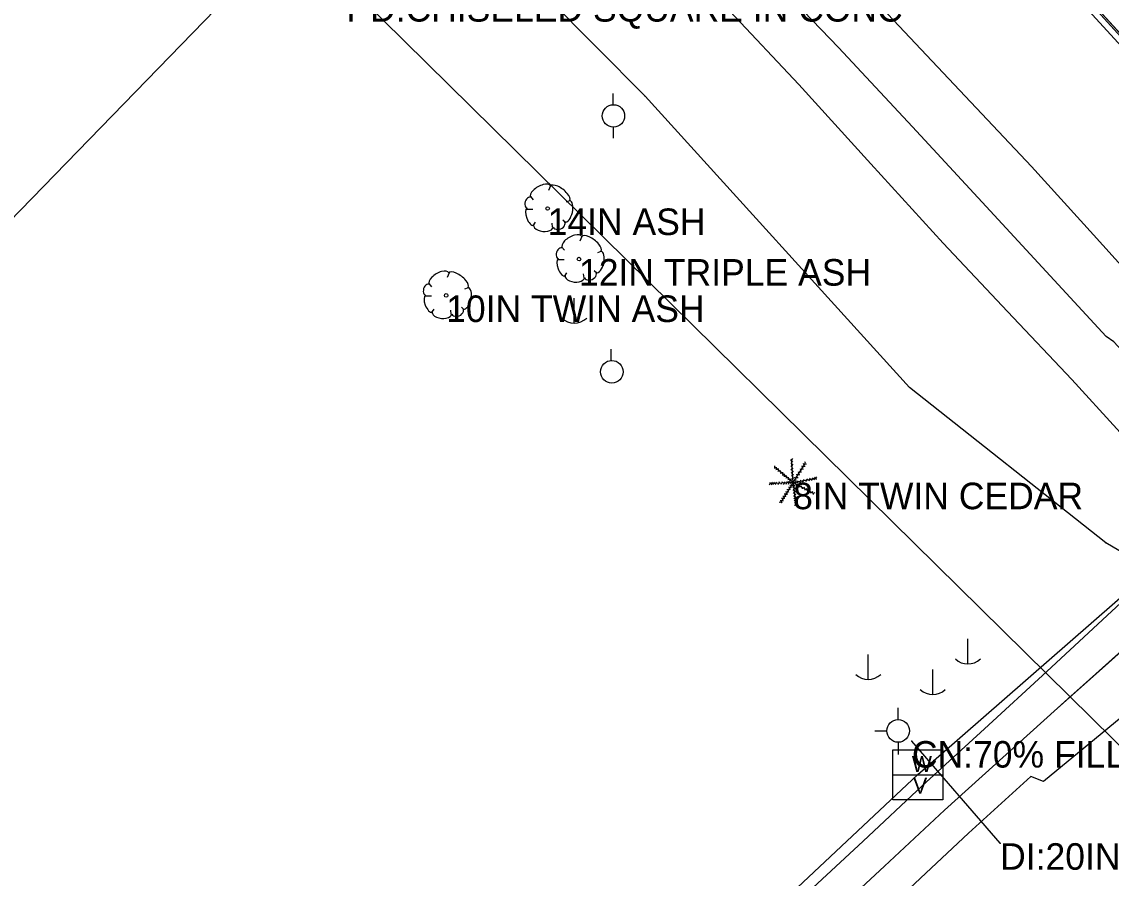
# Model space of a CAD drawing. Extents: x 1660112 to 1662239, y 668919 to 671377.
# Drawn here: x 1661239.8 to 1661444.9, y 669974.4 to 670135.7 of the extents above; entities that cross this region are included whole.
import ezdxf

# ---------------------------------------------------------------- set-up
doc = ezdxf.new("R2010")
doc.units = 0
for name, color, linetype in [('S_DITCHLINE', 7, 'Continuous'), ('S_DRG_PT_SYM', 7, 'Continuous'), ('S_EDGE_PAVEMENT', 7, 'Continuous'), ('S_FENCE', 7, 'Continuous'), ('S_PAVEMENT_CROWN', 7, 'Continuous'), ('S_PRIMARY_CTL_ANNOT', 7, 'Continuous'), ('S_SANITARY_SEWER', 7, 'Continuous'), ('S_SIDE_DRAIN', 7, 'Continuous'), ('S_SIDE_DRAIN_ANNOT', 7, 'Continuous'), ('S_TREE', 7, 'Continuous'), ('S_TREE_ANNOT', 7, 'Continuous'), ('S_UTILITY_POLE', 7, 'Continuous'), ('S_UTL_PT_SYM', 7, 'Continuous'), ('S_WATER_UTILITIES', 7, 'Continuous')]:
    doc.layers.add(name, color=color, linetype=linetype)

msp = doc.modelspace()

# ---------------------------------------------------------------- linework, layer by layer
at = {"layer": 'S_DITCHLINE'}
for points in [[(1661495.46, 670073.89), (1661482.85, 670088.25), (1661470.25, 670102.6), (1661470.41, 670103.23), (1661460.8, 670115.6), (1661451.19, 670127.97), (1661437.9, 670142.65), (1661424.62, 670157.34), (1661411.2, 670172.34), (1661397.77, 670187.35), (1661386.72, 670199.36), (1661375.66, 670211.37), (1661356.56, 670219.75), (1661346.24, 670231.99), (1661335.91, 670244.22), (1661322, 670253.4)], [(1661494.51, 670072.98), (1661481.63, 670087.01), (1661468.75, 670101.04), (1661468.56, 670102.05), (1661459.49, 670114.59), (1661450.42, 670127.12), (1661437.16, 670141.71), (1661423.9, 670156.29), (1661409.97, 670171.2), (1661396.04, 670186.11), (1661384.96, 670198.23), (1661373.87, 670210.36), (1661354.32, 670219.23), (1661344.06, 670230.9), (1661333.8, 670242.57), (1661320.4, 670253.01)]]:
    msp.add_lwpolyline(points, dxfattribs=at)
at = {"layer": 'S_DRG_PT_SYM'}
for points in [[(1661407.39, 670000.2), (1661407.39, 670000.25), (1661407.39, 670000.2), (1661407.34, 670000.2), (1661407.39, 670000.2), (1661407.39, 670000.15), (1661407.39, 670000.2), (1661407.44, 670000.2)], [(1661424, 669980.96), (1661424, 669981.01), (1661424, 669980.96), (1661423.95, 669980.96), (1661424, 669980.96), (1661424, 669980.91), (1661424, 669980.96), (1661424.05, 669980.96)]]:
    msp.add_lwpolyline(points, dxfattribs=at)
at = {"layer": 'S_EDGE_PAVEMENT'}
for points in [[(1661528.89, 670006.64), (1661525.81, 670010.93), (1661521.19, 670007.06), (1661512.12, 670017.42), (1661503.06, 670027.78), (1661494.14, 670038.45), (1661485.22, 670049.12), (1661475.65, 670058.13), (1661469.7, 670064.69), (1661453.26, 670082.63), (1661441.58, 670095.54), (1661429.9, 670108.45), (1661415.33, 670123.89), (1661400.76, 670139.32), (1661387.62, 670152.61), (1661374.47, 670165.9), (1661358.81, 670181.9), (1661343.14, 670197.9), (1661339.48, 670201.44), (1661329.75, 670211.05), (1661320.02, 670220.65), (1661304.77, 670236.19)], [(1661507.57, 669985.17), (1661503.63, 669990.55), (1661503.83, 669996.41), (1661492.59, 670008.33), (1661484.98, 670015.56), (1661475.91, 670025.37), (1661466.84, 670035.18), (1661454.4, 670049.73), (1661445.95, 670059), (1661437.51, 670068.28), (1661425.39, 670081.13), (1661413.28, 670093.99), (1661399.68, 670108.94), (1661386.08, 670123.89), (1661373.13, 670137.66), (1661360.18, 670151.43), (1661345.14, 670167.24), (1661330.11, 670183.04), (1661325.69, 670187.24), (1661316.74, 670196.41), (1661307.8, 670205.57), (1661291.28, 670222.16)], [(1661249.19, 669845.77), (1661252.39, 669848.76), (1661268.86, 669863.99), (1661278.76, 669872.97), (1661288.66, 669881.95), (1661300.04, 669892.31), (1661311.42, 669902.66), (1661327.02, 669916.7), (1661339.16, 669927.65), (1661351.29, 669938.61), (1661369.17, 669954.79), (1661387.06, 669970.96), (1661398.2, 669981.35), (1661409.34, 669991.75), (1661421.08, 670002.53), (1661432.82, 670013.32), (1661449.38, 670028.66), (1661451.32, 670030.24), (1661455.87, 670040.73), (1661454.57, 670045.91), (1661454.4, 670049.73)], [(1661484.97, 670015.57), (1661481.44, 670017.1), (1661474.37, 670019.33), (1661466.03, 670019.66), (1661456.43, 670012.6), (1661444.31, 670002.59), (1661432.19, 669992.58), (1661429.76, 669993.52), (1661418.03, 669982.83), (1661399.88, 669965.82), (1661383.18, 669950.54), (1661366.48, 669935.26), (1661355.84, 669925.69), (1661345.19, 669916.12), (1661334.54, 669906.55), (1661323.9, 669896.98), (1661314.39, 669888.26), (1661304.88, 669879.54), (1661295.37, 669870.82), (1661285.87, 669862.1), (1661271.87, 669849.3), (1661257.87, 669836.51)]]:
    msp.add_lwpolyline(points, dxfattribs=at)
at = {"layer": 'S_FENCE'}
msp.add_line((1661463.18, 670115.3), (1661437.44, 670143.55), dxfattribs=at)
msp.add_lwpolyline([(1661447.01, 670133.04), (1661437.44, 670143.55)], dxfattribs=at)
msp.add_lwpolyline([(1661447.01, 670133.04), (1661437.44, 670143.55)], dxfattribs=at)
at = {"layer": 'S_PAVEMENT_CROWN'}
for points in [[(1661518.06, 669996.03), (1661505.4, 670009.31), (1661492.74, 670022.59), (1661480.19, 670036.99), (1661467.64, 670051.39), (1661473.76, 670044.39), (1661461.34, 670057.98), (1661445.4, 670075.38), (1661443.99, 670076.39), (1661432.69, 670088.65), (1661421.39, 670100.9), (1661407.48, 670115.88), (1661393.57, 670130.85), (1661380.41, 670144.59), (1661367.25, 670158.33), (1661351.88, 670174.26), (1661336.51, 670190.18), (1661332.38, 670194.36), (1661323.21, 670203.51), (1661314.05, 670212.66), (1661297.56, 670228.68)], [(1661253.85, 669840.46), (1661263.61, 669849.85), (1661273.37, 669859.23), (1661283.14, 669868.61), (1661292.9, 669878), (1661304.03, 669887.93), (1661315.16, 669897.86), (1661325.53, 669906.87), (1661335.91, 669915.88), (1661346.29, 669924.88), (1661356.66, 669933.89), (1661373.78, 669949.99), (1661390.9, 669966.09), (1661402.21, 669976.63), (1661413.52, 669987.17), (1661425.13, 669997.67), (1661436.73, 670008.16), (1661454.08, 670023.57), (1661444.42, 670014.94), (1661434.75, 670006.32), (1661450.56, 670020.53), (1661466.37, 670034.74)]]:
    msp.add_lwpolyline(points, dxfattribs=at)
at = {"layer": 'S_SANITARY_SEWER'}
for p, q in [((1661289.08, 670151.19), (1660996.93, 669850.58)), ((1661704.02, 669745.54), (1661292.91, 670150.69))]:
    msp.add_line(p, q, dxfattribs=at)
at = {"layer": 'S_SIDE_DRAIN'}
msp.add_line((1661424, 669980.96), (1661407.39, 670000.2), dxfattribs=at)
at = {"layer": 'S_TREE'}
for p, q in [((1661339.36, 670104.75), (1661338.97, 670103.9)), ((1661335.56, 670102.74), (1661336.06, 670102.16)), ((1661342.92, 670101.96), (1661342.26, 670101.69)), ((1661334.9, 670100.41), (1661336.02, 670100.41)), ((1661336.06, 670097.24), (1661336.53, 670097.93)), ((1661339.74, 670096.97), (1661339.67, 670097.74)), ((1661342.15, 670097.86), (1661341.68, 670098.28)), ((1661345.26, 670095.22), (1661344.88, 670094.37)), ((1661341.47, 670093.21), (1661341.97, 670092.63)), ((1661348.83, 670092.43), (1661348.17, 670092.16)), ((1661340.81, 670090.88), (1661341.93, 670090.88)), ((1661320.25, 670088.37), (1661319.86, 670087.52)), ((1661341.97, 670087.7), (1661342.44, 670088.4)), ((1661345.65, 670087.43), (1661345.57, 670088.21)), ((1661348.05, 670088.32), (1661347.59, 670088.75)), ((1661316.45, 670086.36), (1661316.96, 670085.78)), ((1661323.81, 670085.58), (1661323.16, 670085.31)), ((1661315.79, 670084.03), (1661316.92, 670084.03)), ((1661316.96, 670080.86), (1661317.42, 670081.55)), ((1661320.64, 670080.59), (1661320.56, 670081.36)), ((1661323.04, 670081.48), (1661322.57, 670081.9)), ((1661384.76, 670052.95), (1661384.54, 670053.15)), ((1661384.79, 670052.39), (1661384.57, 670052.59)), ((1661385.02, 670048.87), (1661384.75, 670053.31)), ((1661384.76, 670053.2), (1661384.95, 670053.43)), ((1661384.79, 670052.72), (1661384.98, 670052.96)), ((1661384.82, 670052.12), (1661385.01, 670052.36)), ((1661385.02, 670048.87), (1661387.36, 670052.56)), ((1661387.09, 670052.18), (1661387, 670052.47)), ((1661387.22, 670052.34), (1661387.52, 670052.39)), ((1661387.33, 670052.53), (1661387.24, 670052.81)), ((1661381.73, 670051.62), (1661381.44, 670051.58)), ((1661385.02, 670048.87), (1661381.55, 670051.78)), ((1661381.59, 670051.76), (1661381.59, 670052.06)), ((1661382.08, 670051.34), (1661381.78, 670051.31)), ((1661381.91, 670051.51), (1661381.91, 670051.81)), ((1661382.44, 670051.02), (1661382.14, 670050.99)), ((1661382.26, 670051.22), (1661382.26, 670051.52)), ((1661382.9, 670050.64), (1661382.6, 670050.62)), ((1661382.67, 670050.85), (1661382.67, 670051.15)), ((1661383.26, 670050.31), (1661382.96, 670050.29)), ((1661383.09, 670050.53), (1661383.09, 670050.83)), ((1661383.41, 670050.24), (1661383.41, 670050.54)), ((1661383.78, 670049.94), (1661383.78, 670050.24)), ((1661384.82, 670051.82), (1661384.6, 670052.01)), ((1661384.85, 670051.16), (1661384.62, 670051.36)), ((1661384.89, 670050.56), (1661384.66, 670050.76)), ((1661384.93, 670050), (1661384.7, 670050.2)), ((1661384.86, 670051.41), (1661385.05, 670051.65)), ((1661384.92, 670050.85), (1661385.11, 670051.08)), ((1661384.94, 670050.28), (1661385.12, 670050.51)), ((1661385.82, 670050.16), (1661385.73, 670050.44)), ((1661385.98, 670050.37), (1661386.28, 670050.41)), ((1661386.12, 670050.65), (1661386.03, 670050.93)), ((1661386.33, 670050.89), (1661386.63, 670050.93)), ((1661386.49, 670051.22), (1661386.4, 670051.5)), ((1661386.66, 670051.43), (1661386.95, 670051.47)), ((1661386.79, 670051.73), (1661386.7, 670052.02)), ((1661386.98, 670051.92), (1661387.27, 670051.96)), ((1661380.65, 670048.66), (1661380.51, 670048.39)), ((1661385.02, 670048.87), (1661380.56, 670048.66)), ((1661380.8, 670048.68), (1661380.63, 670048.93)), ((1661381, 670048.69), (1661380.86, 670048.42)), ((1661381.18, 670048.71), (1661381.02, 670048.96)), ((1661381.34, 670048.71), (1661381.2, 670048.44)), ((1661381.58, 670048.71), (1661381.42, 670048.96)), ((1661381.76, 670048.72), (1661381.62, 670048.45)), ((1661381.98, 670048.74), (1661381.82, 670048.98)), ((1661382.27, 670048.74), (1661382.13, 670048.48)), ((1661382.55, 670048.75), (1661382.38, 670049)), ((1661385.02, 670048.87), (1661382.64, 670045.1)), ((1661382.83, 670048.77), (1661382.7, 670048.5)), ((1661383.11, 670048.79), (1661382.94, 670049.04)), ((1661383.31, 670048.79), (1661383.18, 670048.52)), ((1661383.6, 670050.05), (1661383.3, 670050.02)), ((1661383.58, 670048.8), (1661383.42, 670049.05)), ((1661383.94, 670049.75), (1661383.64, 670049.73)), ((1661383.78, 670048.82), (1661383.65, 670048.55)), ((1661384.02, 670048.84), (1661383.85, 670049.09)), ((1661384.31, 670049.45), (1661384.01, 670049.43)), ((1661384.24, 670048.82), (1661384.11, 670048.55)), ((1661384.15, 670049.63), (1661384.15, 670049.93)), ((1661384.36, 670048.88), (1661384.19, 670049.13)), ((1661384.67, 670049.16), (1661384.37, 670049.13)), ((1661384.69, 670048.38), (1661384.39, 670048.34)), ((1661384.5, 670049.32), (1661384.5, 670049.62)), ((1661384.63, 670048.83), (1661384.5, 670048.57)), ((1661384.6, 670048.22), (1661384.67, 670047.93)), ((1661384.94, 670049.38), (1661384.71, 670049.58)), ((1661384.81, 670048.55), (1661384.89, 670048.26)), ((1661385.08, 670048.2), (1661384.88, 670047.97)), ((1661384.96, 670049.61), (1661385.15, 670049.84)), ((1661385.02, 670048.87), (1661389.44, 670049.74)), ((1661385.02, 670048.87), (1661388.93, 670046.83)), ((1661385.02, 670048.87), (1661385.55, 670044.5)), ((1661385.09, 670048.45), (1661385.35, 670048.29)), ((1661385.35, 670048.69), (1661385.61, 670048.83)), ((1661385.36, 670049.36), (1661385.66, 670049.41)), ((1661385.46, 670049.63), (1661385.37, 670049.91)), ((1661385.39, 670048.96), (1661385.59, 670049.18)), ((1661385.53, 670048.6), (1661385.6, 670048.3)), ((1661385.64, 670048.99), (1661385.89, 670048.83)), ((1661385.65, 670049.83), (1661385.95, 670049.87)), ((1661385.79, 670049.02), (1661385.99, 670049.24)), ((1661385.82, 670048.47), (1661386.09, 670048.61)), ((1661386.11, 670048.29), (1661386.18, 670048)), ((1661386.15, 670049.07), (1661386.41, 670048.91)), ((1661386.32, 670049.12), (1661386.52, 670049.34)), ((1661386.38, 670048.16), (1661386.64, 670048.3)), ((1661386.67, 670049.18), (1661386.92, 670049.02)), ((1661386.89, 670049.25), (1661387.09, 670049.47)), ((1661387.27, 670049.31), (1661387.53, 670049.15)), ((1661387.52, 670049.39), (1661387.72, 670049.61)), ((1661387.86, 670049.42), (1661388.11, 670049.26)), ((1661388.12, 670049.48), (1661388.32, 670049.7)), ((1661388.36, 670049.53), (1661388.62, 670049.37)), ((1661388.6, 670049.58), (1661388.8, 670049.81)), ((1661388.79, 670049.62), (1661389.04, 670049.46)), ((1661389.04, 670049.67), (1661389.25, 670049.9)), ((1661389.2, 670049.68), (1661389.45, 670049.52)), ((1661389.27, 670049.73), (1661389.47, 670049.95)), ((1661383.36, 670046.27), (1661383.06, 670046.24)), ((1661383.27, 670046.09), (1661383.35, 670045.8)), ((1661383.66, 670046.73), (1661383.36, 670046.69)), ((1661383.52, 670046.47), (1661383.6, 670046.18)), ((1661383.92, 670047.14), (1661383.62, 670047.11)), ((1661383.8, 670046.94), (1661383.88, 670046.65)), ((1661384.17, 670047.56), (1661383.87, 670047.53)), ((1661384.06, 670047.36), (1661384.14, 670047.07)), ((1661384.45, 670048.01), (1661384.15, 670047.98)), ((1661384.32, 670047.78), (1661384.4, 670047.49)), ((1661385.14, 670047.62), (1661384.95, 670047.39)), ((1661385.23, 670047.06), (1661385.03, 670046.83)), ((1661385.3, 670046.49), (1661385.1, 670046.26)), ((1661385.13, 670047.89), (1661385.39, 670047.74)), ((1661385.22, 670047.33), (1661385.47, 670047.17)), ((1661385.28, 670046.78), (1661385.54, 670046.62)), ((1661385.35, 670046.27), (1661385.61, 670046.11)), ((1661386.64, 670048.02), (1661386.71, 670047.72)), ((1661386.93, 670047.88), (1661387.2, 670048.02)), ((1661387.16, 670047.74), (1661387.24, 670047.45)), ((1661387.42, 670047.62), (1661387.68, 670047.76)), ((1661387.7, 670047.45), (1661387.77, 670047.16)), ((1661387.95, 670047.35), (1661388.22, 670047.49)), ((1661388.22, 670047.19), (1661388.29, 670046.9)), ((1661388.5, 670047.07), (1661388.77, 670047.21)), ((1661388.71, 670046.94), (1661388.78, 670046.65)), ((1661388.89, 670046.87), (1661389.16, 670047.01)), ((1661382.67, 670045.18), (1661382.37, 670045.15)), ((1661382.87, 670045.49), (1661382.57, 670045.45)), ((1661382.79, 670045.34), (1661382.87, 670045.05)), ((1661383.12, 670045.9), (1661382.82, 670045.87)), ((1661383.02, 670045.69), (1661383.09, 670045.4)), ((1661385.36, 670046.03), (1661385.17, 670045.8)), ((1661385.4, 670045.65), (1661385.2, 670045.42)), ((1661385.46, 670045.2), (1661385.26, 670044.98)), ((1661385.5, 670044.78), (1661385.31, 670044.56)), ((1661385.38, 670045.83), (1661385.64, 670045.68)), ((1661385.43, 670045.43), (1661385.69, 670045.27)), ((1661385.49, 670044.96), (1661385.75, 670044.81)), ((1661385.53, 670044.62), (1661385.79, 670044.47))]:
    msp.add_line(p, q, dxfattribs=at)
for centre in [(1661338.8, 670100.51), (1661344.71, 670090.98), (1661319.69, 670084.13)]:
    msp.add_circle(centre, 0.341, dxfattribs=at)
for centre, major_axis, ratio, start_param, end_param in [((1661337.46, 670103.71), (1.86, 1.08), 0.471018, 0, 3.141593), ((1661341.12, 670103.39), (-1.81, 1.36), 0.405113, 3.141593, 6.283186), ((1661335.23, 670101.6), (0.31, 1.03), 0.646762, 0, 3.141593), ((1661342.47, 670099.98), (0.46, 2.04), 0.482994, 3.141593, 6.283185), ((1661335.53, 670098.95), (-0.61, 1.6), 0.420543, 6.283185, 9.424777), ((1661337.99, 670097.17), (-1.83, 0.19), 0.529943, 0, 3.141593), ((1661340.95, 670097.46), (1.09, 0.46), 0.711534, 3.141592, 6.283185), ((1661343.37, 670094.18), (1.86, 1.08), 0.471018, 0, 3.141593), ((1661347.03, 670093.86), (-1.81, 1.36), 0.405113, 3.141593, 6.283186), ((1661341.14, 670092.06), (0.31, 1.03), 0.646762, 0, 3.141593), ((1661348.38, 670090.45), (0.46, 2.04), 0.482994, 3.141593, 6.283185), ((1661341.44, 670089.41), (-0.61, 1.6), 0.420543, 6.283185, 9.424777), ((1661318.35, 670087.33), (1.86, 1.08), 0.471018, 0, 3.141593), ((1661322.01, 670087.01), (-1.81, 1.36), 0.405113, 3.141593, 6.283186), ((1661343.9, 670087.63), (-1.83, 0.19), 0.529943, 0, 3.141593), ((1661346.86, 670087.93), (1.09, 0.46), 0.711534, 3.141592, 6.283185), ((1661316.12, 670085.22), (0.31, 1.03), 0.646762, 0, 3.141593), ((1661323.37, 670083.6), (0.46, 2.04), 0.482994, 3.141593, 6.283185), ((1661316.43, 670082.57), (-0.61, 1.6), 0.420543, 6.283185, 9.424777), ((1661318.89, 670080.79), (-1.83, 0.19), 0.529943, 0, 3.141593), ((1661321.84, 670081.08), (1.09, 0.46), 0.711534, 3.141592, 6.283185)]:
    msp.add_ellipse(centre, major_axis=major_axis, ratio=ratio, start_param=start_param, end_param=end_param, dxfattribs=at)
at = {"layer": 'S_UTILITY_POLE'}
for p, q in [((1661351.17, 670120.02), (1661351.17, 670122.15)), ((1661351.17, 670115.8), (1661351.17, 670113.74)), ((1661343.74, 670083.65), (1661343.74, 670078.92)), ((1661350.76, 670071.9), (1661350.76, 670074.01)), ((1661417.87, 670019.44), (1661417.87, 670014.71)), ((1661399.11, 670016.52), (1661399.11, 670011.79)), ((1661411.26, 670013.67), (1661411.26, 670008.95)), ((1661404.81, 670004.22), (1661404.81, 670006.47)), ((1661402.72, 670002.09), (1661400.39, 670002.09)), ((1661404.89, 669997.68), (1661404.89, 670000))]:
    msp.add_line(p, q, dxfattribs=at)
for centre, radius in [((1661351.19, 670117.94), 2.11), ((1661350.88, 670069.76), 2.13), ((1661404.81, 670002.11), 2.13)]:
    msp.add_circle(centre, radius, dxfattribs=at)
for centre in [(1661343.81, 670082.34), (1661417.93, 670018.14), (1661399.17, 670015.22), (1661411.32, 670012.37)]:
    msp.add_arc(centre, 3.41, 226.3972, 313.6028, dxfattribs=at)
at = {"layer": 'S_UTL_PT_SYM'}
for points in [[(1661357.16, 670121.64), (1661357.16, 670121.69), (1661357.16, 670121.64), (1661357.11, 670121.64), (1661357.16, 670121.64), (1661357.16, 670121.58), (1661357.16, 670121.64), (1661357.21, 670121.64)], [(1661406.96, 670066.82), (1661406.96, 670066.87), (1661406.96, 670066.82), (1661406.91, 670066.82), (1661406.96, 670066.82), (1661406.96, 670066.77), (1661406.96, 670066.82), (1661407.01, 670066.82)], [(1661443.91, 670037.56), (1661443.91, 670037.61), (1661443.91, 670037.56), (1661443.86, 670037.56), (1661443.91, 670037.56), (1661443.91, 670037.51), (1661443.91, 670037.56), (1661443.96, 670037.56)], [(1661408.52, 669993.88), (1661408.52, 669993.93), (1661408.52, 669993.88), (1661408.47, 669993.88), (1661408.52, 669993.88), (1661408.52, 669993.83), (1661408.52, 669993.88), (1661408.57, 669993.88)]]:
    msp.add_lwpolyline(points, dxfattribs=at)
at = {"layer": 'S_WATER_UTILITIES'}
for p, q in [((1661357.16, 670121.64), (1661319.59, 670159.62)), ((1661406.96, 670066.82), (1661357.16, 670121.64)), ((1661443.91, 670037.56), (1661406.96, 670066.82)), ((1661452.55, 670032.39), (1661443.91, 670037.56)), ((1661408.52, 669993.88), (1661452.54, 670032.42)), ((1661403.83, 669998.54), (1661413.24, 669998.54)), ((1661403.83, 669989.12), (1661403.83, 669998.54)), ((1661413.24, 669998.54), (1661413.24, 669989.12)), ((1661371.87, 669959.59), (1661408.52, 669993.88)), ((1661403.83, 669993.85), (1661413.24, 669993.85)), ((1661413.24, 669989.12), (1661403.83, 669989.12))]:
    msp.add_line(p, q, dxfattribs=at)

# ---------------------------------------------------------------- texts
at = {"layer": 'S_PRIMARY_CTL_ANNOT'}
msp.add_text('PD:CHISELED SQUARE IN CONC', height=5, dxfattribs=at).set_placement((1661300.89, 670135.71))
at = {"layer": 'S_SIDE_DRAIN_ANNOT'}
for s, p in [('CN:70% FILL INVERT OF PIPE', (1661407.39, 669995.2)), ('DI:20INX9IN CN:70% FILL CRUSHED CMP', (1661424, 669975.96))]:
    msp.add_text(s, height=5, dxfattribs=at).set_placement(p)
at = {"layer": 'S_TREE_ANNOT'}
for s, p in [('14IN ASH', (1661338.8, 670095.51)), ('12IN TRIPLE ASH', (1661344.71, 670085.98)), ('10IN TWIN ASH', (1661319.69, 670079.13)), ('8IN TWIN CEDAR', (1661385.02, 670043.87))]:
    msp.add_text(s, height=5, dxfattribs=at).set_placement(p)
at = {"layer": 'S_WATER_UTILITIES'}
for s, p in [('W', (1661407.38, 669994.38)), ('V', (1661407.61, 669990.32))]:
    msp.add_text(s, height=3, rotation=360, dxfattribs=at).set_placement(p)

doc.saveas('drawing.dxf')
